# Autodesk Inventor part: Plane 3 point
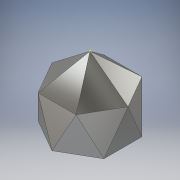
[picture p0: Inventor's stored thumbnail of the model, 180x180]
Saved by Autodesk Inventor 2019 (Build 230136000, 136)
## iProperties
Created: 2018-12
Part Number: Plane 3 point
Material: Nickel-Copper Alloy 400
Document SubType Name: Modeling
Designer: Synergysoft
Density: 8.83 g/cm^3
Appearance: Chrome - Polished
Author: Synergysoft
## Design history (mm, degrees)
sketch "Sketch1"
  geometry: L1 (0, -3000)-(-2598.076, -1500); L2 (-2598.076, -1500)-(-2598.076, 1500); L3 (-2598.076, 1500)-(0, 3000); L4 (0, 3000)-(2598.076, 1500); L5 (2598.076, 1500)-(2598.076, -1500); L6 (2598.076, -1500)-(0, -3000); 3 further points
  constraints: 12 end point, 1 coincident, 1 horizontal alignment, 1 midpoint, 13 other
  dimensions: "d0" = 6000 distance of L3.end L1.start
workplane "Work Plane1"
sketch "Sketch2"
  geometry: L1 (3000, 0)-(1500, -2598.076); L2 (1500, -2598.076)-(-1500, -2598.076); L3 (-1500, -2598.076)-(-3000, 0); L4 (-3000, 0)-(-1500, 2598.076); L5 (-1500, 2598.076)-(1500, 2598.076); L6 (1500, 2598.076)-(3000, 0); 3 further points
  constraints: 12 end point, 1 coincident, 1 midpoint, 1 vertical alignment, 13 other
  dimensions: "d17" = 6000 distance of L3.end L1.start (= d0)
feature "Sculpt1"
  workplane "Work Plane2"
  workplane "Work Plane3"
  workplane "Work Plane4"
  workplane "Work Plane5"
  workplane "Work Plane6"
  workplane "Work Plane7"
  workplane "Work Plane8"
  workplane "Work Plane9"
  workplane "Work Plane10"
  workplane "Work Plane11"
  workplane "Work Plane12"
  workplane "Work Plane13"
workplane "Work Plane16"
workplane "Work Plane17"
workpoint "Work Point1"
  workaxis "Work Axis1"
  workaxis "Work Axis2"
feature "Sculpt2"
  workplane "Work Plane18"
  workplane "Work Plane19"
  workplane "Work Plane20"
  workplane "Work Plane21"
  workplane "Work Plane22"
  workplane "Work Plane23"
body "Solid1"
